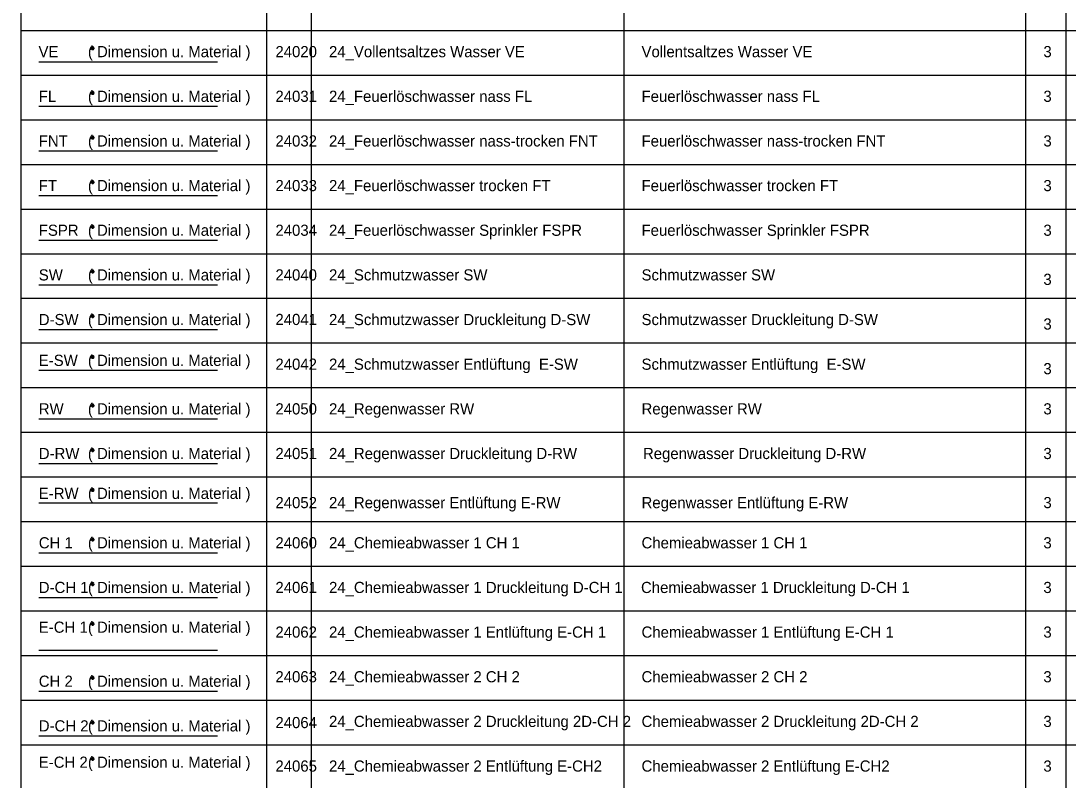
# Model space of a CAD drawing. Extents: x -14.5 to 23.8, y -56.3 to 8.
# Drawn here: x 0 to 11.73, y -15.39 to -6.89 of the extents above; entities that cross this region are included whole.
import ezdxf

# ---------------------------------------------------------------- set-up
doc = ezdxf.new("R2010")
doc.units = 0
for name, color, linetype in [('24_Chemieabwasser 1 CH 1', 7, 'Continuous'), ('24_Chemieabwasser 1 Druckleitung CH 1', 7, 'Continuous'), ('24_Chemieabwasser 1 Entlüftung E-CH 1', 7, 'Continuous'), ('24_Chemieabwasser 2 CH 2', 7, 'Continuous'), ('24_Chemieabwasser 2 Druckleitung CH 2', 7, 'Continuous'), ('24_Chemieabwasser 2 Entlüftung E-CH2', 7, 'Continuous'), ('24_Feuerlöschwasser nass FL', 7, 'Continuous'), ('24_Feuerlöschwasser nass-trocken FNT', 7, 'Continuous'), ('24_Feuerlöschwasser Sprinkler FSPR', 7, 'Continuous'), ('24_Feuerlöschwasser trocken FT', 7, 'Continuous'), ('24_Regenwasser Druckleitung D-RW', 7, 'Continuous'), ('24_Regenwasser Entlüftung E-RW', 7, 'Continuous'), ('24_Regenwasser RW', 7, 'Continuous'), ('24_Schmutzwasser Druckleitung D-SW', 7, 'Continuous'), ('24_Schmutzwasser Entlüftung  E-SW', 7, 'Continuous'), ('24_Schmutzwasser SW', 7, 'Continuous'), ('24_Vollentsaltzes Wasser VE', 7, 'Continuous'), ('Default', 7, 'Continuous')]:
    doc.layers.add(name, color=color, linetype=linetype)

msp = doc.modelspace()

# ---------------------------------------------------------------- linework, layer by layer
at = {"layer": '24_Chemieabwasser 1 CH 1'}
for p, q in [((0.778, -12.7), (0.822, -12.7)), ((0.784, -12.684), (0.816, -12.716)), ((0.816, -12.684), (0.784, -12.716)), ((0.8, -12.678), (0.8, -12.722)), ((0.2, -12.85), (2.2, -12.85))]:
    msp.add_line(p, q, dxfattribs=at)
at = {"layer": '24_Chemieabwasser 1 Druckleitung CH 1'}
for p, q in [((0.778, -13.2), (0.822, -13.2)), ((0.784, -13.184), (0.816, -13.216)), ((0.816, -13.184), (0.784, -13.216)), ((0.8, -13.178), (0.8, -13.222)), ((0.2, -13.35), (2.2, -13.35))]:
    msp.add_line(p, q, dxfattribs=at)
at = {"layer": '24_Chemieabwasser 1 Entlüftung E-CH 1'}
for p, q in [((0.778, -13.645), (0.822, -13.645)), ((0.784, -13.629), (0.816, -13.66)), ((0.816, -13.629), (0.784, -13.66)), ((0.8, -13.623), (0.8, -13.667)), ((0.2, -13.939), (2.2, -13.939))]:
    msp.add_line(p, q, dxfattribs=at)
at = {"layer": '24_Chemieabwasser 2 CH 2'}
for p, q in [((0.778, -14.25), (0.822, -14.25)), ((0.784, -14.234), (0.816, -14.266)), ((0.816, -14.234), (0.784, -14.266)), ((0.8, -14.228), (0.8, -14.272)), ((0.2, -14.4), (2.2, -14.4)), ((0.778, -14.75), (0.822, -14.75)), ((0.784, -14.734), (0.816, -14.766)), ((0.816, -14.734), (0.784, -14.766)), ((0.8, -14.728), (0.8, -14.772))]:
    msp.add_line(p, q, dxfattribs=at)
at = {"layer": '24_Chemieabwasser 2 Druckleitung CH 2'}
msp.add_line((0.2, -14.9), (2.2, -14.9), dxfattribs=at)
at = {"layer": '24_Chemieabwasser 2 Entlüftung E-CH2'}
for p, q in [((0.778, -15.157), (0.822, -15.157)), ((0.784, -15.141), (0.816, -15.172)), ((0.816, -15.141), (0.784, -15.172)), ((0.8, -15.134), (0.8, -15.179))]:
    msp.add_line(p, q, dxfattribs=at)
at = {"layer": '24_Feuerlöschwasser nass FL'}
for p, q in [((0.778, -7.7), (0.822, -7.7)), ((0.784, -7.684), (0.816, -7.716)), ((0.816, -7.684), (0.784, -7.716)), ((0.8, -7.678), (0.8, -7.722)), ((0.2, -7.85), (2.2, -7.85))]:
    msp.add_line(p, q, dxfattribs=at)
at = {"layer": '24_Feuerlöschwasser nass-trocken FNT'}
for p, q in [((0.778, -8.2), (0.822, -8.2)), ((0.784, -8.184), (0.816, -8.216)), ((0.816, -8.184), (0.784, -8.216)), ((0.8, -8.178), (0.8, -8.222)), ((0.2, -8.35), (2.2, -8.35))]:
    msp.add_line(p, q, dxfattribs=at)
at = {"layer": '24_Feuerlöschwasser Sprinkler FSPR'}
for p, q in [((0.778, -9.2), (0.822, -9.2)), ((0.784, -9.184), (0.816, -9.216)), ((0.816, -9.184), (0.784, -9.216)), ((0.8, -9.178), (0.8, -9.222)), ((0.2, -9.35), (2.2, -9.35))]:
    msp.add_line(p, q, dxfattribs=at)
at = {"layer": '24_Feuerlöschwasser trocken FT'}
for p, q in [((0.778, -8.7), (0.822, -8.7)), ((0.784, -8.684), (0.816, -8.716)), ((0.816, -8.684), (0.784, -8.716)), ((0.8, -8.678), (0.8, -8.722)), ((0.2, -8.85), (2.2, -8.85))]:
    msp.add_line(p, q, dxfattribs=at)
at = {"layer": '24_Regenwasser Druckleitung D-RW'}
msp.add_line((0.2, -11.85), (2.2, -11.85), dxfattribs=at)
at = {"layer": '24_Regenwasser Entlüftung E-RW'}
for p, q in [((0.778, -12.146), (0.822, -12.146)), ((0.784, -12.131), (0.816, -12.162)), ((0.816, -12.131), (0.784, -12.162)), ((0.8, -12.124), (0.8, -12.168)), ((0.2, -12.29), (2.2, -12.29))]:
    msp.add_line(p, q, dxfattribs=at)
at = {"layer": '24_Regenwasser RW'}
for p, q in [((0.778, -11.2), (0.822, -11.2)), ((0.784, -11.184), (0.816, -11.216)), ((0.816, -11.184), (0.784, -11.216)), ((0.8, -11.178), (0.8, -11.222)), ((0.2, -11.35), (2.2, -11.35)), ((0.778, -11.7), (0.822, -11.7)), ((0.784, -11.684), (0.816, -11.716)), ((0.816, -11.684), (0.784, -11.716)), ((0.8, -11.678), (0.8, -11.722))]:
    msp.add_line(p, q, dxfattribs=at)
at = {"layer": '24_Schmutzwasser Druckleitung D-SW'}
msp.add_line((0.2, -10.35), (2.2, -10.35), dxfattribs=at)
at = {"layer": '24_Schmutzwasser Entlüftung  E-SW'}
for p, q in [((0.778, -10.657), (0.822, -10.657)), ((0.784, -10.641), (0.816, -10.673)), ((0.816, -10.641), (0.784, -10.673)), ((0.8, -10.635), (0.8, -10.679)), ((0.2, -10.803), (2.2, -10.803))]:
    msp.add_line(p, q, dxfattribs=at)
at = {"layer": '24_Schmutzwasser SW'}
for p, q in [((0.778, -9.7), (0.822, -9.7)), ((0.784, -9.684), (0.816, -9.716)), ((0.816, -9.684), (0.784, -9.716)), ((0.8, -9.678), (0.8, -9.722)), ((0.2, -9.85), (2.2, -9.85)), ((0.778, -10.2), (0.822, -10.2)), ((0.784, -10.184), (0.816, -10.216)), ((0.816, -10.184), (0.784, -10.216)), ((0.8, -10.178), (0.8, -10.222))]:
    msp.add_line(p, q, dxfattribs=at)
at = {"layer": '24_Vollentsaltzes Wasser VE'}
for p, q in [((0.778, -7.2), (0.822, -7.2)), ((0.784, -7.184), (0.816, -7.216)), ((0.816, -7.184), (0.784, -7.216)), ((0.8, -7.178), (0.8, -7.222)), ((0.2, -7.35), (2.2, -7.35))]:
    msp.add_line(p, q, dxfattribs=at)
at = {"layer": 'Default'}
for p, q in [((0, 0), (0, -53.5)), ((2.75, 0), (2.75, -53.5)), ((3.25, 0), (3.25, -53.5)), ((6.75, 0), (6.75, -53.5)), ((11.25, 0), (11.25, -53.5)), ((11.7, -0.35), (11.7, -44.5)), ((0, -7), (16, -7)), ((0, -7.5), (16, -7.5)), ((0, -8), (16, -8)), ((0, -8.5), (16, -8.5)), ((0, -9), (16, -9)), ((0, -9.5), (16, -9.5)), ((0, -10), (16, -10)), ((0, -10.5), (16, -10.5)), ((0, -11), (16, -11)), ((0, -11.5), (16, -11.5)), ((0, -12), (16, -12)), ((0, -12.5), (16, -12.5)), ((0, -13), (16, -13)), ((0, -13.5), (16, -13.5)), ((0, -14), (16, -14)), ((0, -14.5), (16, -14.5)), ((0, -15), (16, -15))]:
    msp.add_line(p, q, dxfattribs=at)

# ---------------------------------------------------------------- texts
at = {"layer": '24_Chemieabwasser 1 CH 1'}
for s, p in [('CH 1', (0.2, -12.8)), ('( Dimension u. Material )', (0.75, -12.8))]:
    msp.add_text(s, height=0.125, dxfattribs=at).set_placement(p)
at = {"layer": '24_Chemieabwasser 1 Druckleitung CH 1'}
for s, p in [('D-CH 1', (0.2, -13.3)), ('( Dimension u. Material )', (0.75, -13.3))]:
    msp.add_text(s, height=0.125, dxfattribs=at).set_placement(p)
at = {"layer": '24_Chemieabwasser 1 Entlüftung E-CH 1'}
for s, p in [('E-CH 1', (0.2, -13.745)), ('( Dimension u. Material )', (0.75, -13.745))]:
    msp.add_text(s, height=0.125, dxfattribs=at).set_placement(p)
at = {"layer": '24_Chemieabwasser 2 CH 2'}
for s, p in [('CH 2', (0.2, -14.35)), ('( Dimension u. Material )', (0.75, -14.35))]:
    msp.add_text(s, height=0.125, dxfattribs=at).set_placement(p)
at = {"layer": '24_Chemieabwasser 2 Druckleitung CH 2'}
for s, p in [('D-CH 2', (0.2, -14.85)), ('( Dimension u. Material )', (0.75, -14.85))]:
    msp.add_text(s, height=0.125, dxfattribs=at).set_placement(p)
at = {"layer": '24_Chemieabwasser 2 Entlüftung E-CH2'}
for s, p in [('( Dimension u. Material )', (0.75, -15.257)), ('E-CH 2', (0.2, -15.257))]:
    msp.add_text(s, height=0.125, dxfattribs=at).set_placement(p)
at = {"layer": '24_Feuerlöschwasser nass FL'}
for s, p in [('FL', (0.2, -7.8)), ('( Dimension u. Material )', (0.75, -7.8))]:
    msp.add_text(s, height=0.125, dxfattribs=at).set_placement(p)
at = {"layer": '24_Feuerlöschwasser nass-trocken FNT'}
for s, p in [('FNT', (0.2, -8.3)), ('( Dimension u. Material )', (0.75, -8.3))]:
    msp.add_text(s, height=0.125, dxfattribs=at).set_placement(p)
at = {"layer": '24_Feuerlöschwasser Sprinkler FSPR'}
for s, p in [('FSPR', (0.2, -9.3)), ('( Dimension u. Material )', (0.75, -9.3))]:
    msp.add_text(s, height=0.125, dxfattribs=at).set_placement(p)
at = {"layer": '24_Feuerlöschwasser trocken FT'}
for s, p in [('FT', (0.2, -8.8)), ('( Dimension u. Material )', (0.75, -8.8))]:
    msp.add_text(s, height=0.125, dxfattribs=at).set_placement(p)
at = {"layer": '24_Regenwasser Druckleitung D-RW'}
for s, p in [('D-RW', (0.2, -11.8)), ('( Dimension u. Material )', (0.75, -11.8))]:
    msp.add_text(s, height=0.125, dxfattribs=at).set_placement(p)
at = {"layer": '24_Regenwasser Entlüftung E-RW'}
for s, p in [('E-RW', (0.2, -12.246)), ('( Dimension u. Material )', (0.75, -12.246))]:
    msp.add_text(s, height=0.125, dxfattribs=at).set_placement(p)
at = {"layer": '24_Regenwasser RW'}
for s, p in [('RW', (0.2, -11.3)), ('( Dimension u. Material )', (0.75, -11.3))]:
    msp.add_text(s, height=0.125, dxfattribs=at).set_placement(p)
at = {"layer": '24_Schmutzwasser Druckleitung D-SW'}
msp.add_text('( Dimension u. Material )', height=0.125, dxfattribs=at).set_placement((0.75, -10.3))
at = {"layer": '24_Schmutzwasser Entlüftung  E-SW'}
for s, p in [('E-SW', (0.2, -10.757)), ('( Dimension u. Material )', (0.75, -10.757))]:
    msp.add_text(s, height=0.125, dxfattribs=at).set_placement(p)
at = {"layer": '24_Schmutzwasser SW'}
for s, p in [('SW', (0.2, -9.8)), ('( Dimension u. Material )', (0.75, -9.8)), ('D-SW', (0.2, -10.3))]:
    msp.add_text(s, height=0.125, dxfattribs=at).set_placement(p)
at = {"layer": '24_Vollentsaltzes Wasser VE'}
for s, p in [('VE', (0.197, -7.3)), ('( Dimension u. Material )', (0.75, -7.3))]:
    msp.add_text(s, height=0.125, dxfattribs=at).set_placement(p)
at = {"layer": 'Default'}
for s, p in [('24020', (2.85, -7.3)), ('24_Vollentsaltzes Wasser VE', (3.45, -7.3)), ('Vollentsaltzes Wasser VE', (6.95, -7.3)), ('3', (11.45, -7.3)), ('24031', (2.85, -7.8)), ('24_Feuerlöschwasser nass FL', (3.45, -7.8)), ('Feuerlöschwasser nass FL', (6.95, -7.8)), ('3', (11.45, -7.8)), ('24032', (2.85, -8.3)), ('24_Feuerlöschwasser nass-trocken FNT', (3.45, -8.3)), ('Feuerlöschwasser nass-trocken FNT', (6.95, -8.3)), ('3', (11.45, -8.3)), ('24033', (2.85, -8.8)), ('24_Feuerlöschwasser trocken FT', (3.45, -8.8)), ('Feuerlöschwasser trocken FT', (6.95, -8.8)), ('3', (11.45, -8.8)), ('24034', (2.85, -9.3)), ('24_Feuerlöschwasser Sprinkler FSPR', (3.45, -9.3)), ('Feuerlöschwasser Sprinkler FSPR', (6.95, -9.3)), ('3', (11.45, -9.3)), ('24040', (2.85, -9.8)), ('24_Schmutzwasser SW', (3.45, -9.8)), ('Schmutzwasser SW', (6.95, -9.8)), ('3', (11.45, -9.85)), ('24041', (2.85, -10.299)), ('24_Schmutzwasser Druckleitung D-SW', (3.45, -10.3)), ('Schmutzwasser Druckleitung D-SW', (6.95, -10.3)), ('3', (11.45, -10.35)), ('24_Schmutzwasser Entlüftung  E-SW', (3.45, -10.8)), ('Schmutzwasser Entlüftung  E-SW', (6.95, -10.8)), ('24042', (2.85, -10.8)), ('3', (11.45, -10.85)), ('24050', (2.85, -11.3)), ('24_Regenwasser RW', (3.45, -11.3)), ('Regenwasser RW', (6.95, -11.3)), ('3', (11.45, -11.3)), ('24051', (2.85, -11.8)), ('24_Regenwasser Druckleitung D-RW', (3.45, -11.8)), ('Regenwasser Druckleitung D-RW', (6.966, -11.8)), ('3', (11.45, -11.8)), ('24052', (2.85, -12.35)), ('24_Regenwasser Entlüftung E-RW', (3.45, -12.35)), ('Regenwasser Entlüftung E-RW', (6.95, -12.35)), ('3', (11.45, -12.35)), ('24060', (2.85, -12.8)), ('24_Chemieabwasser 1 CH 1', (3.45, -12.8)), ('Chemieabwasser 1 CH 1', (6.95, -12.8)), ('3', (11.45, -12.8)), ('24061', (2.85, -13.3)), ('24_Chemieabwasser 1 Druckleitung D-CH 1', (3.45, -13.3)), ('Chemieabwasser 1 Druckleitung D-CH 1', (6.944, -13.3)), ('3', (11.45, -13.3)), ('24062', (2.85, -13.8)), ('24_Chemieabwasser 1 Entlüftung E-CH 1', (3.45, -13.8)), ('Chemieabwasser 1 Entlüftung E-CH 1', (6.95, -13.8)), ('3', (11.45, -13.8)), ('24063', (2.85, -14.3)), ('24_Chemieabwasser 2 CH 2', (3.45, -14.3)), ('Chemieabwasser 2 CH 2', (6.95, -14.3)), ('3', (11.45, -14.3)), ('24064', (2.85, -14.813)), ('24_Chemieabwasser 2 Druckleitung 2D-CH 2', (3.45, -14.8)), ('Chemieabwasser 2 Druckleitung 2D-CH 2', (6.95, -14.8)), ('3', (11.45, -14.8)), ('24065', (2.85, -15.3)), ('24_Chemieabwasser 2 Entlüftung E-CH2', (3.45, -15.3)), ('Chemieabwasser 2 Entlüftung E-CH2', (6.95, -15.3)), ('3', (11.45, -15.3))]:
    msp.add_text(s, height=0.125, dxfattribs=at).set_placement(p)

doc.saveas('drawing.dxf')
